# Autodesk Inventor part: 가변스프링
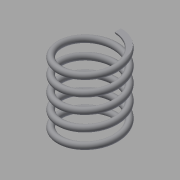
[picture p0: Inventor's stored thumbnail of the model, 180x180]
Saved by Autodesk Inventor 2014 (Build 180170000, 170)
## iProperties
Created: 2018-12
Part Number: 가변스프링
Material: Generic
Document SubType Name: Modeling
Designer: kh
Density: 1 g/cm^3
Appearance: Default
Author: kh
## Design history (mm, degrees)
sketch "Sketch1"
  geometry: L1 (0, 0)-(9, 0); L2 (9, 0)-(9, 24.5); L3 (9, 24.5)-(0, 24.5); L4 (0, 24.5)-(0, 0); C1 r 1 at (9, 0)
  constraints: 8 end point, 2 parallel, 1 centre point, 1 coincident, 1 horizontal, 1 perpendicular
  dimensions: "d0" = 2 diameter of C1; "d1" = 18 diameter of L2 L4; "d2" = 24.5 distance of L1.end L2.end (derived)
coil "Coil1" sketch "Sketch1" pitch "d3" = 10; turns "d5" = 5; dims "d4" = 24.5 (= d2), "d6" = 0, angle "d7" = 90 deg, angle "d8" = 90 deg, "d9" = 0, "d10" = 0
workplane "Work Plane1"
workplane "Work Plane2"
split "Split1"
split "Split2"
body "Solid1"
other parameters: "d11" = 0, "d12" = 24.5 (= d2)
